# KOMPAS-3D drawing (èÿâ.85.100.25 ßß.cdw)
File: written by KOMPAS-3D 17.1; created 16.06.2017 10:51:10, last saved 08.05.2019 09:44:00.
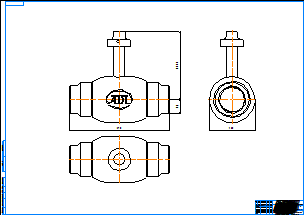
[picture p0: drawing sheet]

Sheet 1: A0, landscape

Title block, sheet 1: name: КШГ.85.100.25 сс; material: Внимание! Данный продукт является объектом авторского права ООО «Торговый Дом АДЛ». / Запрещается изменение, копирование, распространение / (в том числе путем копирования на другие сайты и ресурсы в Интернете) / или любое иное использование информации и объектов без предварительного / согласия правообладателя (ООО «Торговый Дом АДЛ»).; scale: 1:1; sheets: 1; organisation: ООО "Торговый дом АДЛ"; sheet format: A0; stored path: C:\Users\tra\Desktop\2д чертежи\Шаровые краны БИВАЛ\КШ_Бивал_серия_82_85\KOMPAS 2D\КШГ.85.100.25 сс.cdw

Views: Спереди 1, Проекционный вид 2, Проекционный вид 3
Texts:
  Klimkovich
  ADL
Dimensions and other numbers on the sheet: 390; 266,9; 54; 180; 1:1; 1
